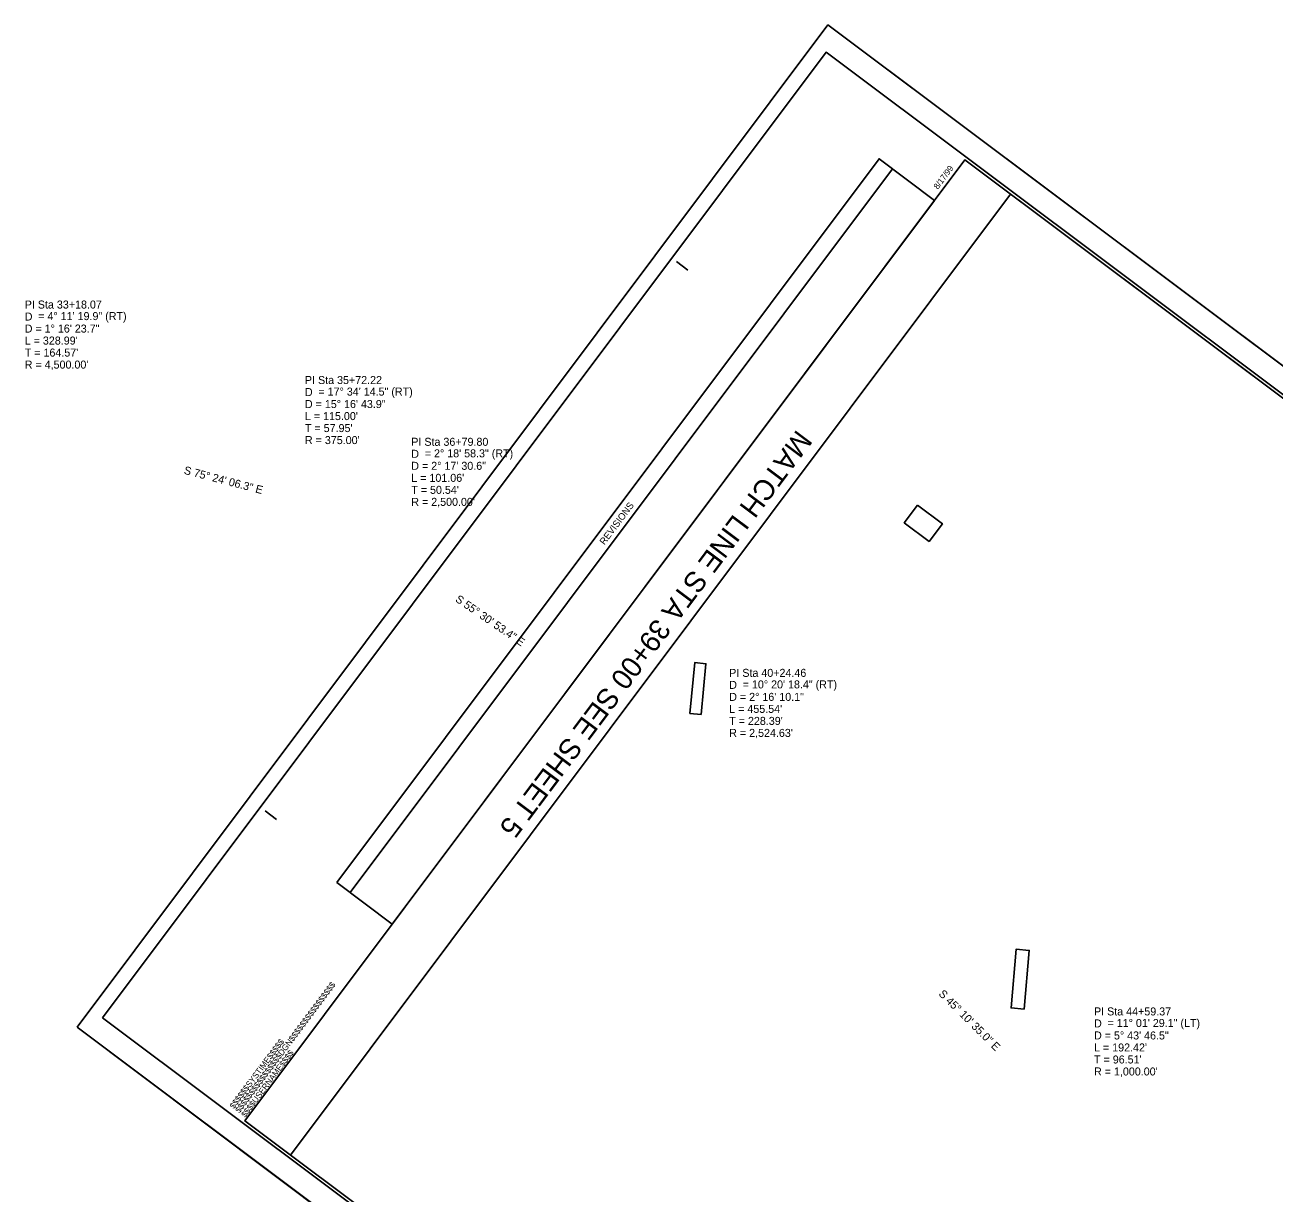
# Model space of a CAD drawing. Extents: x 928111 to 937215, y 684180 to 686530.
# Drawn here: x 930144 to 931236, y 685045 to 686066 of the extents above; entities that cross this region are included whole.
import ezdxf

# ---------------------------------------------------------------- set-up
doc = ezdxf.new("R2010")
doc.units = 0
for name, color, linetype in [('Exist Horizontal Alignment Curve and Spiral Data', 7, 'Continuous'), ('Exist Horizontal Alignment Direction Label', 7, 'Continuous'), ('Matchline', 7, 'Continuous'), ('Matchline Text', 7, 'Continuous'), ('Prop DSN Text', 7, 'Continuous'), ('Sheet Cutting Line CELL', 7, 'Continuous'), ('Sheet Layout Plan Border', 7, 'Continuous'), ('Sheet Plan CELL', 7, 'Continuous'), ('Sheet Plan Layout CELL', 7, 'Continuous'), ('Sheet Plot Border Inside CELL', 7, 'Continuous'), ('Sheet Plot Border Outside CELL', 7, 'Continuous')]:
    doc.layers.add(name, color=color, linetype=linetype)

msp = doc.modelspace()

# ---------------------------------------------------------------- linework, layer by layer
at = {"layer": 'Matchline'}
msp.add_line((930376.5, 685077.8), (931006.1, 685918.1), dxfattribs=at)
at = {"layer": 'Prop DSN Text'}
for points in [[(930924.6, 685646.2), (930946.4, 685629.9), (930934.8, 685614.4), (930913, 685630.8)], [(930735.5, 685463.2), (930739.6, 685507.5), (930729.9, 685508.5), (930725.7, 685464.1)], [(931017.8, 685205.5), (931022.3, 685256.9), (931010.9, 685257.9), (931006.5, 685206.5)]]:
    msp.add_lwpolyline(points, close=True, dxfattribs=at)
at = {"layer": 'Sheet Cutting Line CELL'}
for p, q in [((930846.3, 686065.9), (930189.7, 685189.6)), ((932193.6, 685056.4), (930846.3, 686065.9)), ((930189.7, 685189.6), (931537, 684180.1))]:
    msp.add_line(p, q, dxfattribs=at)
at = {"layer": 'Sheet Layout Plan Border'}
msp.add_line((931006.1, 685918.1), (930376.5, 685077.8), dxfattribs=at)
at = {"layer": 'Sheet Plan CELL'}
for p, q in [((930428.6, 685307.4), (930902.7, 685940.1)), ((930966.1, 685948.1), (930966.1, 685948.1)), ((930713.8, 685859), (930723.8, 685851.6)), ((930354.1, 685378.9), (930364.1, 685371.4)), ((930336.5, 685107.8), (930336.5, 685107.8))]:
    msp.add_line(p, q, dxfattribs=at)
for points in [[(930416.9, 685316.1), (930891, 685948.9), (930939.5, 685912.6), (930465.4, 685279.8)], [(932166.5, 685048.6), (930966.1, 685948.1), (930336.5, 685107.8), (931536.9, 684208.3)]]:
    msp.add_lwpolyline(points, close=True, dxfattribs=at)
at = {"layer": 'Sheet Plan Layout CELL'}
msp.add_lwpolyline([(930966.1, 685948.1), (930336.5, 685107.8), (931536.9, 684208.3), (932039.7, 684879.4), (931848.2, 685022.8), (931975, 685192.1)], close=True, dxfattribs=at)
at = {"layer": 'Sheet Plot Border Inside CELL'}
msp.add_lwpolyline([(930212.1, 685197.8), (931545.4, 684198.8), (932178, 685043.1), (930844.7, 686042.1)], close=True, dxfattribs=at)
at = {"layer": 'Sheet Plot Border Outside CELL'}
msp.add_lwpolyline([(930189.7, 685189.6), (931537, 684180.1), (932193.6, 685056.4), (930846.3, 686065.9)], close=True, dxfattribs=at)

# ---------------------------------------------------------------- texts
at = {"layer": 'Exist Horizontal Alignment Curve and Spiral Data'}
for s, p in [('PI Sta 33+18.07', (930144, 685818)), ('D', (930144, 685807.5)), ('= 4%%d 11\' 19.9" (RT)', (930155.8, 685807.9)), ('D = 1%%d 16\' 23.7"', (930144, 685797)), ("L = 328.99'", (930144, 685786.5)), ("T = 164.57'", (930144, 685776)), ("R = 4,500.00'", (930144, 685765.5)), ('PI Sta 35+72.22', (930389, 685752)), ('D', (930389, 685741.5)), ('= 17%%d 34\' 14.5" (RT)', (930400.8, 685741.9)), ('D = 15%%d 16\' 43.9"', (930389, 685731)), ("L = 115.00'", (930389, 685720.5)), ("T = 57.95'", (930389, 685710)), ("R = 375.00'", (930389, 685699.5)), ('PI Sta 36+79.80', (930482, 685698)), ('D', (930482, 685687.5)), ('= 2%%d 18\' 58.3" (RT)', (930493.8, 685687.9)), ('D = 2%%d 17\' 30.6"', (930482, 685677)), ("L = 101.06'", (930482, 685666.5)), ("T = 50.54'", (930482, 685656)), ("R = 2,500.00'", (930482, 685645.5)), ('PI Sta 40+24.46', (930760, 685496)), ('D', (930760, 685485.5)), ('= 10%%d 20\' 18.4" (RT)', (930771.8, 685485.9)), ('D = 2%%d 16\' 10.1"', (930760, 685475)), ("L = 455.54'", (930760, 685464.5)), ("T = 228.39'", (930760, 685454)), ("R = 2,524.63'", (930760, 685443.5)), ('PI Sta 44+59.37', (931079, 685200)), ('D', (931079, 685189.5)), ('= 11%%d 01\' 29.1" (LT)', (931090.8, 685189.9)), ('D = 5%%d 43\' 46.5"', (931079, 685179)), ("L = 192.42'", (931079, 685168.5)), ("T = 96.51'", (931079, 685158)), ("R = 1,000.00'", (931079, 685147.5))]:
    msp.add_text(s, height=7, dxfattribs=at).set_placement(p)
at = {"layer": 'Exist Horizontal Alignment Direction Label'}
for s, rotation, p in [('S 75%%d 24\' 06.3" E', 345.4017, (930282.7, 685673.6)), ('S 55%%d 30\' 53.4" E', 325.5148, (930519.9, 685562.4)), ('S 45%%d 10\' 35.0" E', 315.1764, (930942.6, 685218.3))]:
    msp.add_text(s, height=7, rotation=rotation, dxfattribs=at).set_placement(p)
at = {"layer": 'Matchline Text'}
msp.add_text('MATCH LINE STA 39+00 SEE SHEET 5', height=18, rotation=233.1562, dxfattribs=at).set_placement((930819.3, 685712.9))
at = {"layer": 'Sheet Plan CELL'}
for s, height, p in [('8/17/99', 5.25, (930942.4, 685921.8)), ('REVISIONS', 6, (930650.9, 685610.9)), ('$$$$$$$$$$$$$$$$DGN$$$$$$$$$$$$$$$$', 5.25, (930331.8, 685114.3)), ('$$$$$$SYSTIME$$$$$', 5.25, (930326.9, 685117.9)), ('$$$$USERNAME$$$$', 5.25, (930337, 685110.3))]:
    msp.add_text(s, height=height, rotation=53.1562, dxfattribs=at).set_placement(p)

doc.saveas('drawing.dxf')
